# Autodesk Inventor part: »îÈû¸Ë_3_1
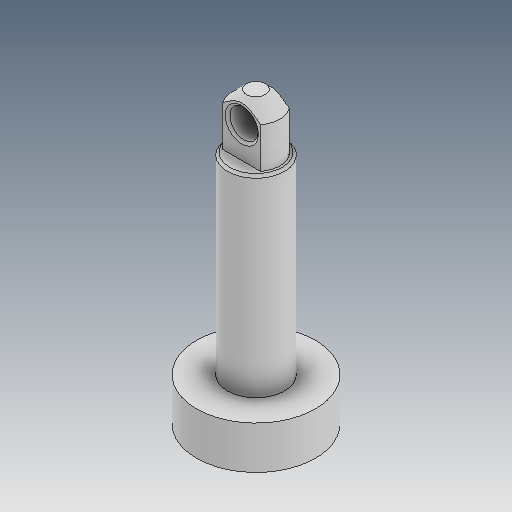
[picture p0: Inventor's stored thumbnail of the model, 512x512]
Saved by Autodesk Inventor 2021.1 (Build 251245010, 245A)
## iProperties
Created: 2019-04
Part Number: »îÈû¸Ë_3_1
Material: Ogólny
Document SubType Name: Modeling
Designer: user
Density: 1 g/cm^3
Appearance: Domyślna
Author: user
Revision Number: ÈÎºÎ
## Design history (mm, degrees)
feature "ÊäÈë1"
node "Bryła1"
